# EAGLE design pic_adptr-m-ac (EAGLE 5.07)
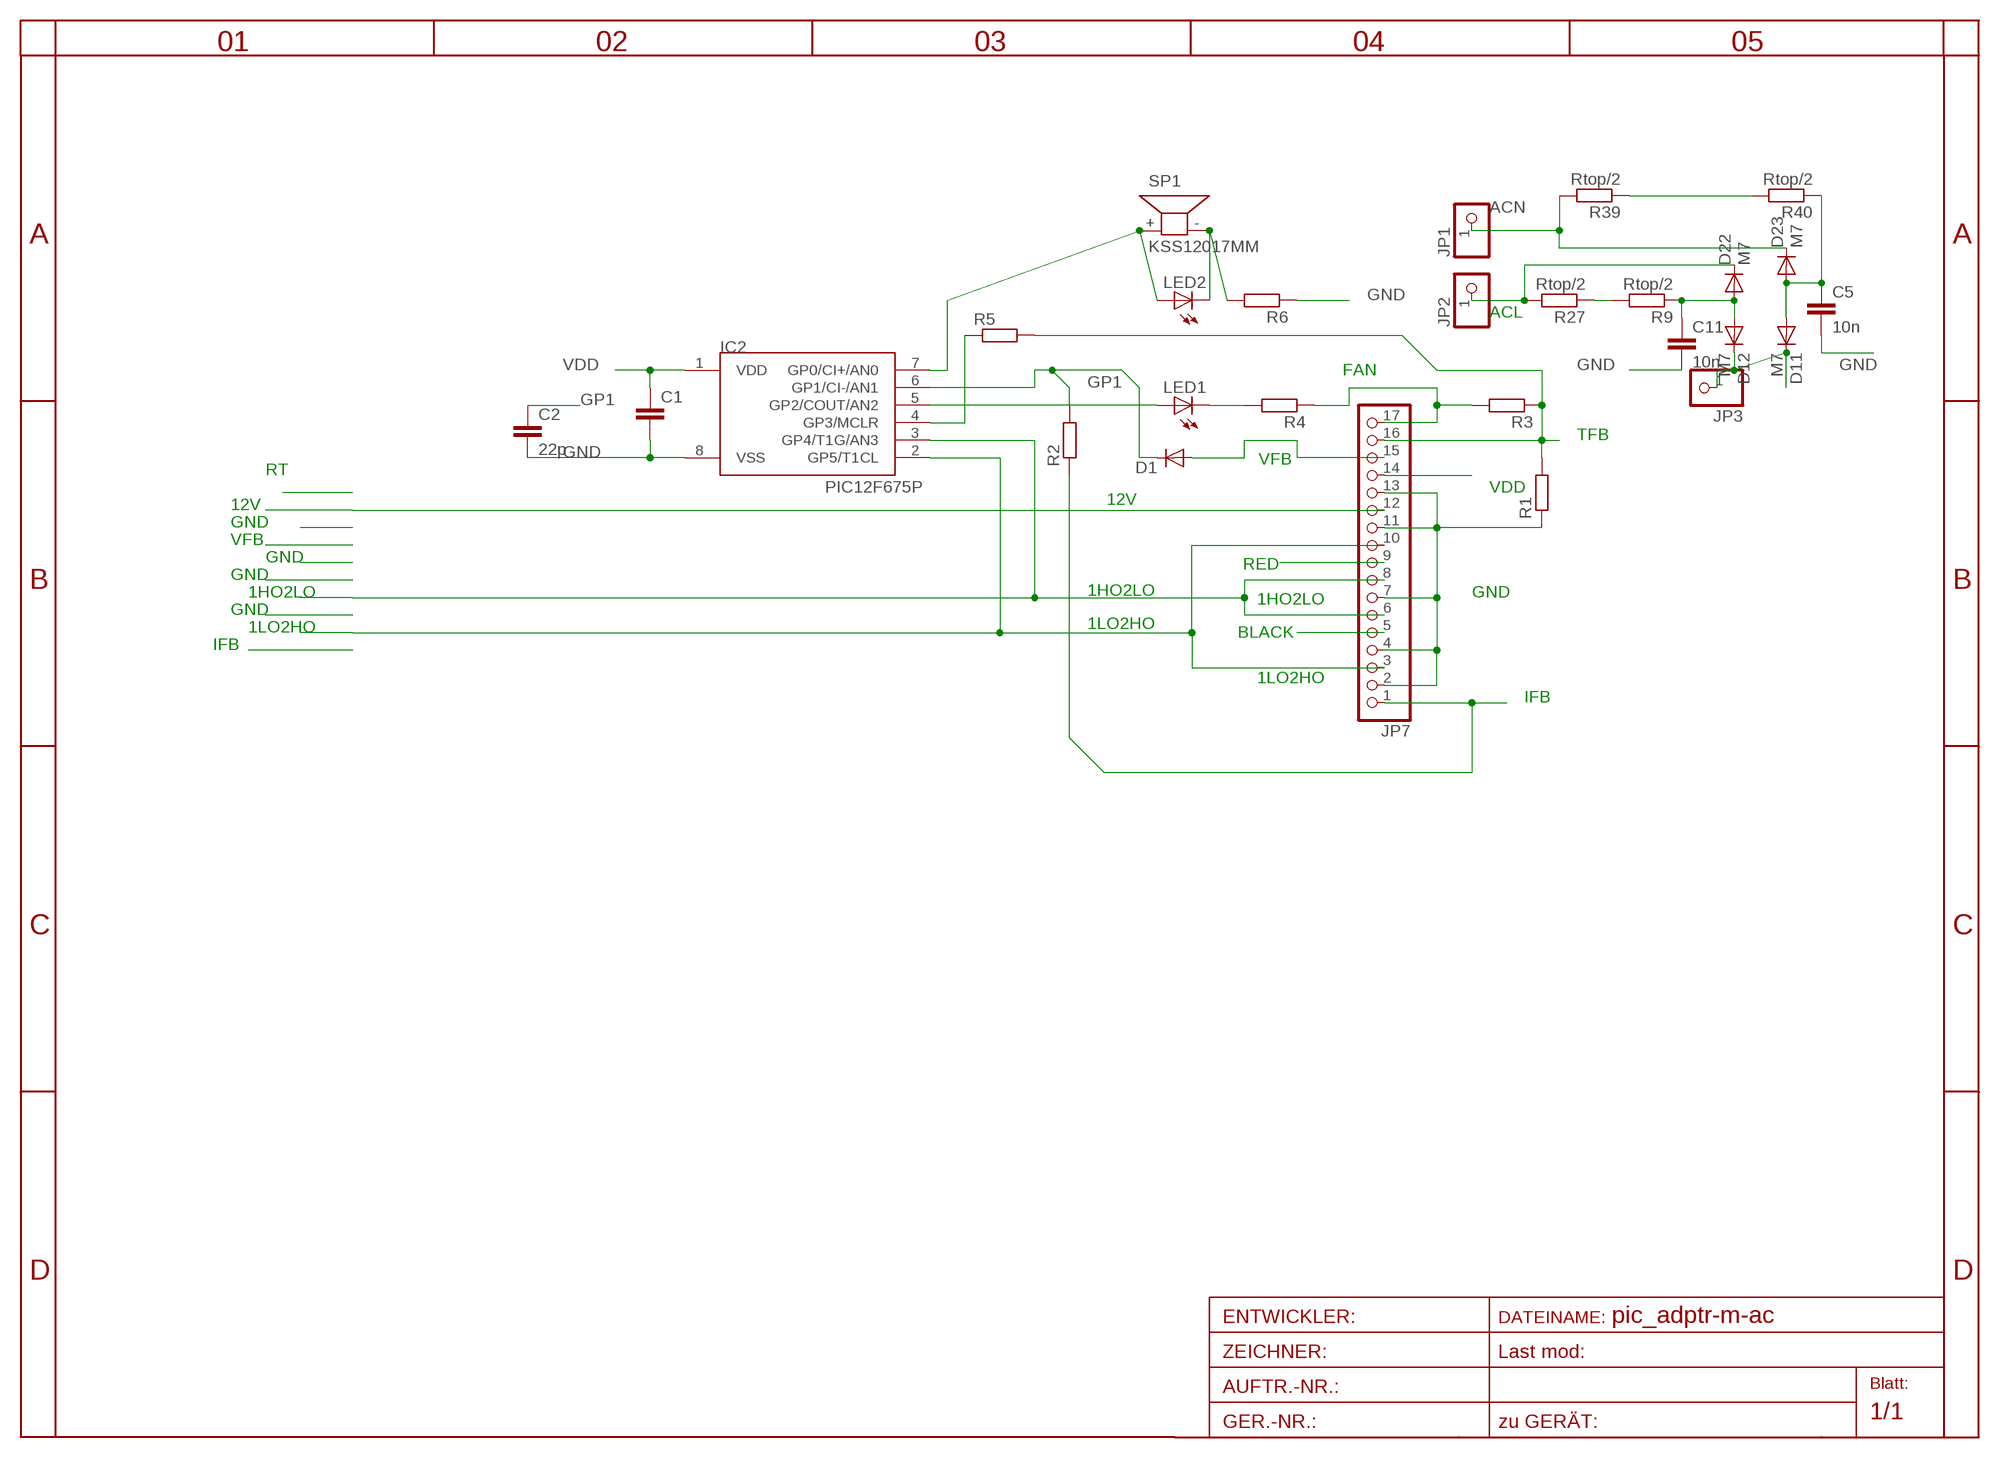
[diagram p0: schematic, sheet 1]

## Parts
C1  C-EUC1206  [C1206]
C2  22p  C-EUC0805  [C0805]
C5  10n  C-EUC1206  [C1206]
C11  10n  C-EUC1206  [C1206]
D1  DIODE-MINIMELF  [MINIMELF]
D11  M7  DIODE-SMA-DO214  [SMA-DO214AC]
D12  M7  DIODE-SMA-DO214  [SMA-DO214AC]
D22  M7  DIODE-SMA-DO214  [SMA-DO214AC]
D23  M7  DIODE-SMA-DO214  [SMA-DO214AC]
IC2  PIC12F675P  [DIL8]
JP1  PINHD-1X11X0.4  [1X01]
JP2  PINHD-1X11X0.4  [1X01]
JP3  PINHD-1X11X0.4  [1X01]
JP7  PINHD-1X17  [1X17]
LED1  LEDCHIPLED_1206  [CHIPLED_1206]
LED2  LEDCHIPLED_1206  [CHIPLED_1206]
R1  R-EU_R1206  [R1206]
R2  R-EU_R0805  [R0805]
R3  R-EU_R0805  [R0805]
R4  R-EU_R0805  [R0805]
R5  R-EU_R0805  [R0805]
R6  R-EU_R0805  [R0805]
R9  Rtop/2  R-EU_R1206  [R1206]
R27  Rtop/2  R-EU_R1206  [R1206]
R39  Rtop/2  R-EU_R1206  [R1206]
R40  Rtop/2  R-EU_R1206  [R1206]
SP1  KSS12017MM  [KSS1202]

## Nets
1HO2LO: IC2.3(GP4/T1G/AN3) JP7.6 JP7.8
1LO2HO: IC2.2(GP5/T1CL) JP7.3 JP7.10
12V: JP7.12
ACL: D22.K(C) JP2.1 R27.2
ACN: D23.K(C) JP1.1 R39.2
BLACK: JP7.5
FAN: JP7.17 R3.2 R4.1
GND: C1.2 C2.2 C5.2 C11.2 IC2.8(VSS) JP7.2 JP7.4 JP7.7 JP7.11 JP7.13 R1.1 R6.1
GP1: C2.1 D1.C IC2.6(GP1/CI-/AN1) R2.2
IFB: JP7.1 R2.1
N$1: IC2.5(GP2/COUT/AN2) LED1.A
N$2: LED1.C R4.2
N$3: IC2.4(GP3/MCLR) R5.1
N$4: IC2.7(GP0/CI+/AN0) LED2.A SP1.+
N$5: LED2.C R6.2 SP1.-
N$11: C11.1 D12.A D22.A R9.1
N$15: R39.1 R40.2
N$19: C5.1 D11.A D23.A R40.1
N$23: R9.2 R27.1
N$30: D11.K(C) D12.K(C) JP3.1
RED: JP7.9
TFB: JP7.16 R1.2 R3.1 R5.2
VDD: C1.1 IC2.1(VDD) JP7.14
VFB: D1.A JP7.15

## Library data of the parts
C1 C2 C5 C11 = rcl:C-EU: CAPACITOR, European symbol
D1 D11 D12 D22 D23 = diode:DIODE-: DIODE
IC2 = microchip-5:PIC12F6*: uPC nW 1k Program Flash memory 2x Timer Comparator 10b A/D converter/ 4xIN
JP1-JP3 = pinhead:PINHD-1X1: PIN HEADER
JP7 = pinhead:PINHD-1X17: PIN HEADER
LED1 LED2 = led:LED: LED
R1-R6 = rcl:R-EU_: RESISTOR, European symbol
R9 R27 R39 R40 = rcl-2:R-EU_: RESISTOR, European symbol
SP1 = buzzer:KSS1201: SPEAKER

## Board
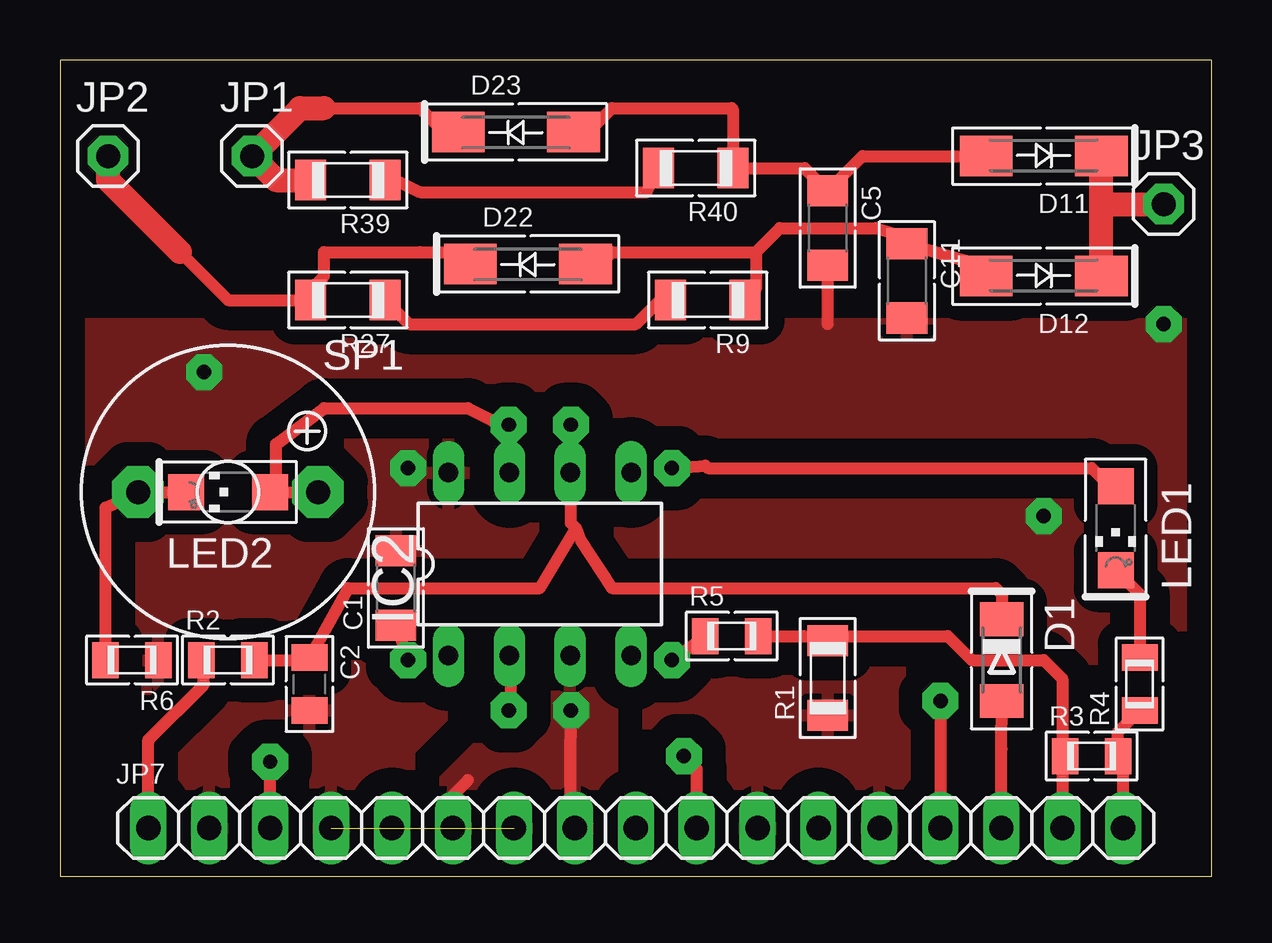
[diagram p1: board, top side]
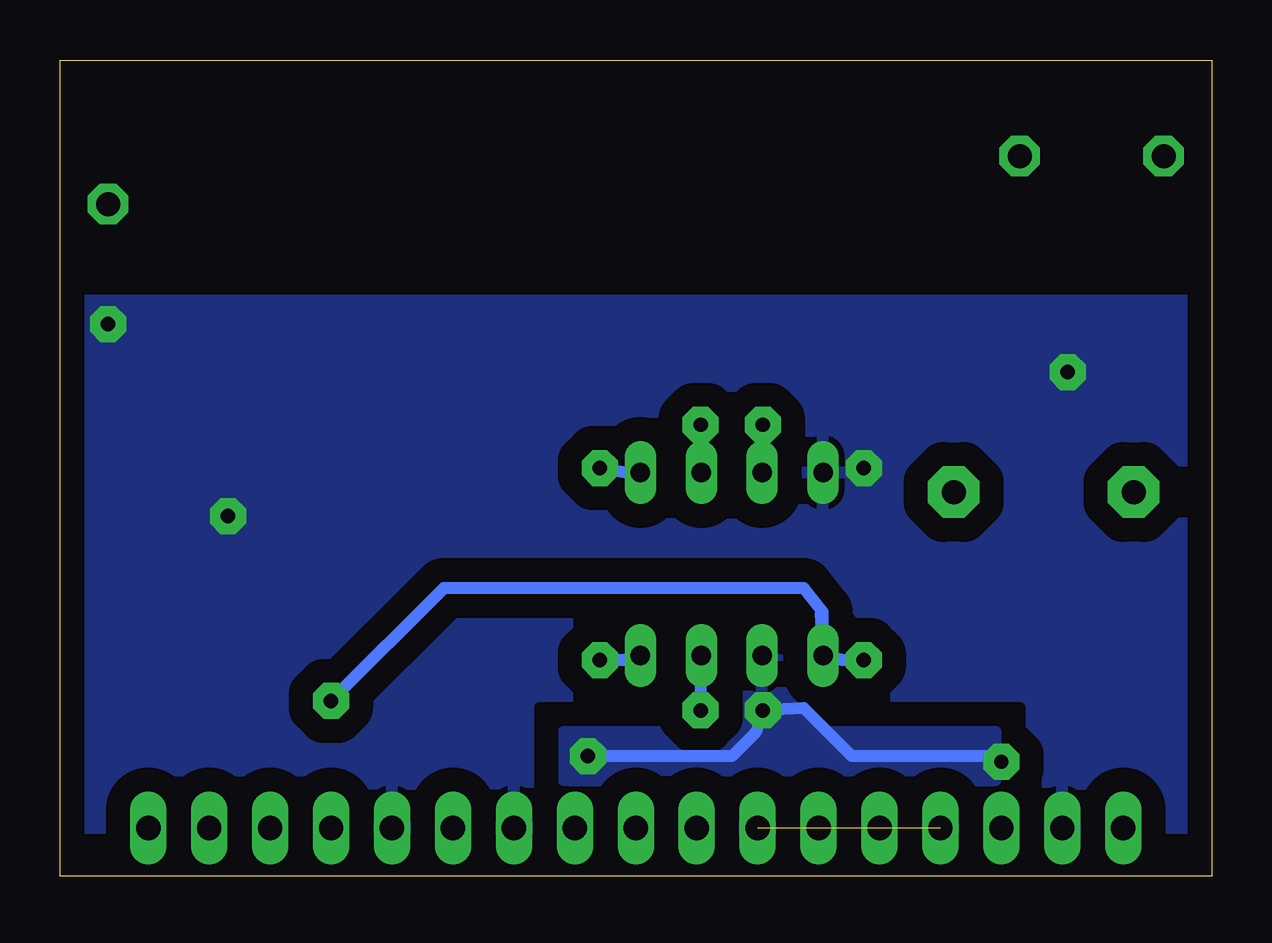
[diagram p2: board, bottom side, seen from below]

Size 48 x 34 mm. Coordinates in mm from the lower left corner, seen from the top.
Outline: 0,0 48,0 48,34 0,34 0,0
Copper layers (1*16): Top 0.035mm / dielectric 1.5mm / Bottom 0.035mm
Design rules "default *": minimum track width 10mil, minimum drill 20mil, track to track 8mil, track to pad 8mil, pad to pad 8mil, via to via 8mil, smd to smd 8mil, copper to edge 40mil, drill to drill 8mil, minimum pad ring 10mil, minimum via ring 8mil, stop-mask expansion 4mil, vias tented up to drill 0mil, thermal gap 10mil

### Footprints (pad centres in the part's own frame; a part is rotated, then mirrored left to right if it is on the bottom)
C1206 = smd 1.3 x 1.7: 1 -1.55,0; 2 1.55,0
C0805 = smd 1.1 x 1.5: 1 -1.1,0; 2 1.1,0
MINIMELF = smd 1.4 x 1.8: A 1.7,0; C -1.7,0
SMA-DO214AC = smd 2.2 x 1.7: A 2.4,0; K -2.4,0
DIL8 = drill 0.8 long: 1 -3.81,-3.81; 2 -1.27,-3.81; 3 1.27,-3.81; 4 3.81,-3.81; 5 3.81,3.81; 6 1.27,3.81; 7 -1.27,3.81; 8 -3.81,3.81
1X01 = drill 1 pad 1.676 octagon: 1 0,0
1X17 = drill 1.016 long: 1 -20.32,0; 2 -17.78,0; 3 -15.24,0; 4 -12.7,0; 5 -10.16,0; 6 -7.62,0; 7 -5.08,0; 8 -2.54,0; 9 0,0; 10 2.54,0; 11 5.08,0; 12 7.62,0; 13 10.16,0; 14 12.7,0; 15 15.24,0; 16 17.78,0; 17 20.32,0
CHIPLED_1206 = smd 1.5 x 1.5: A 0,-1.75; C 0,1.75
R1206 = smd 1.3 x 1.7: 1 -1.55,0; 2 1.55,0
R0805 = smd 1.1 x 1.5: 1 -1.1,0; 2 1.1,0
KSS1202 = drill 1 pad 2.159 octagon: + 3.75,0; - -3.75,0

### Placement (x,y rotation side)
C1  14,12 90 top
C2  10.4,8 270 top
C5  32,27 270 top
C11  35.3,24.8 270 top
D1  39.25,9 270 top
D11  41,30 180 top
D12  41,25 180 top
D22  19.5,25.5 0 top
D23  19,31 0 top
IC2  20,13 0 top
JP1  8,30 0 top
JP2  2,30 0 top
JP3  46,28 0 top
JP7  24,2 0 top
LED1  44,14.5 180 top
LED2  7,16 90 top
R1  32,8.25 90 top
R2  7,9 0 top
R3  43,5 0 top
R4  45,8 90 top
R5  28,10 0 top
R6  3,9 180 top
R9  27,24 180 top
R27  12,24 180 top
R39  12,29 180 top
R40  26.5,29.5 180 top
SP1  7,16 0 top

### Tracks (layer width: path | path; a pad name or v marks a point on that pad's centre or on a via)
1HO2LO  (via drill 0.6 pad 1.5)
  Top 0.5: v21.3,6.9 21.27,2.19 JP7.8 | 17,4 16,3 16,2.38 JP7.6
  Bottom 0.5: v21.3,6.9 IC2.3
  pour Top (isolate 1, rank 2): 20,8 23,8 23,1 21,1 21,3 18,3 18,2 17,1 15,1 15,3
1LO2HO  (via drill 0.6 pad 1.5)
  Top 0.5: JP7.3 v8.76,4.76 | JP7.10 26.54,4.46 v26,5 | v18.7,6.9 18.8,7.6 18.8,9.1
  Bottom 0.5: v8.76,4.76 9,5 15,5 16,6 17,7 v18.7,6.9 19,6 20,5 v26,5 | IC2.2 19,8.92 IC2.2
  pour Bottom (isolate 1): 19,9 20,8 20,7 21,6 27,6 27,4 9,4 9,6 16,6 17,7 17,8 18,9
ACL
  Top 0.5: 5,26 7,24 R27.2 10.45,24.45 11,25 11,26 15,26 17,26 D22.K
  Top 1: 5,26 2,29 JP2.1
ACN
  Top 0.5: D23.K 16,31 15,32 11,32
  Top 1: R39.2 9,29 JP1.1 10,32 11,32
FAN
  Top 0.5: JP7.17 44.32,4.78 R3.2 44.1,6 R4.1
GND  (via drill 0.6 pad 1.5)  (1 unrouted)
  Top 0.5: 32,23 C5.2
  other vias: 46,23 14.5,17 41,15 6,21
  pour Top (isolate 1, rank 3): 47,23 1,23 1,1 47,1
  pour Bottom (isolate 1, rank 3): 47,24 1,24 1,2 47,2
GP1  (via drill 0.6 pad 1.5)
  Top 0.5: 21.5,14.5 21.7,14 23,12 39,12 39.25,11.75 D1.C | 21.5,14.5 20,12 12,12 C2.1 10.3,9 R2.2 | v21.3,18.8 21.3,16.3 21.3,14.7 21.5,14.5
  Bottom 0.5: IC2.6 21.27,18.77 v21.3,18.8
IFB
  Top 0.5: JP7.1 3.68,5.58 3.68,5.68 6,8 R2.1
N$1  (via drill 0.6 pad 1.5)
  Top 0.5: v25.5,17 26.9,17.1 27,17 43,17 44,16 LED1.A
  Bottom 0.5: IC2.5 24.41,16.81 v25.5,17
N$2
  Top 0.5: R4.2 45,11.75 LED1.C
N$3  (via drill 0.6 pad 1.5)
  Top 0.5: v25.5,9 R5.1
  Bottom 0.5: v25.5,9 24.52,9 IC2.4
N$4  (via drill 0.6 pad 1.5)
  Top 0.5: v18.7,18.8 18.2,18.8 18,19 17,19.5 11,19.5 9,18 9,16.25 LED2.A SP1.+
  Bottom 0.5: IC2.7 18.73,18.77 v18.7,18.8
N$5
  Top 0.5: LED2.C SP1.- 1.9,15.35 R6.2
N$11
  Top 0.5: 29,26 30,27 34,27 35.45,26.55 C11.1 38.05,25.55 D12.A | 29,26 29,24.45 R9.1 | D22.A 22,25 23,26 29,26
N$15
  Top 0.5: R39.1 14,29 15,28.5 24.45,28.5 R40.2
N$19
  Top 0.5: D23.A 22,31 23,32 28,32 28.05,31.95 R40.1 31.05,29.5 C5.1 33.45,30 D11.A
N$23
  Top 0.5: R9.2 25,24 24,23 14.55,23 R27.1
N$30
  Top 0.5: 43.4,25.4 43,25 D12.K
  Top 1: 43.4,25.4 43.4,28 | 43.4,28 D11.K | 43.4,28 JP3.1
TFB
  Top 0.5: 41.78,4.88 JP7.16 | 41.78,4.88 R3.1 | 41.78,4.88 41.78,8.22 41,9 38,9 37,10 31,10 | 31,10 31.8,10 R1.2 | R5.2 31,10
VDD  (via drill 0.6 pad 1.5)
  Top 0.5: v36.7,7.3 JP7.14 | C1.1 v14.5,9
  Bottom 0.5: v36.7,7.3 32,12 17,12 16.2,11 16.2,9.48 IC2.1 | IC2.1 16.28,11 | v14.5,9 15.38,9 IC2.1
VFB
  Top 0.5: JP7.15 39.24,5.29 D1.A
